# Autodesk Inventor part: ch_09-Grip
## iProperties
Shininess: 0.0
Length Units: 11272
Angle Units: 11279
Time Units: 11290
Mass Units: 11283
Length Display Precision: 2
Angle Display Precision: 1
Created: 1999-05
Part Number: ch_09-Grip
Document SubType Name: Modeling
Designer: Administrator
Density: 1 g/cm^3
Density: 0.0
Volumn: 0.0
Area: 0.0
PropertySet Name: Model Information
Control State: 0
Master: False
Checked Out: False
Author: Administrator
